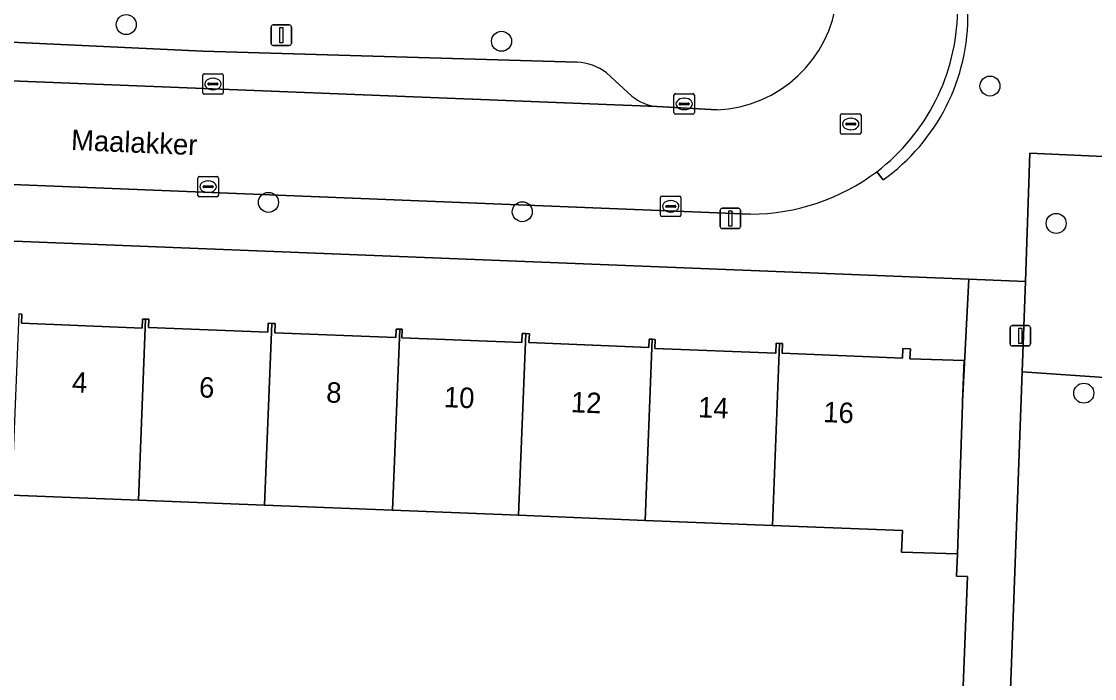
# Model space of a CAD drawing. Extents: x 161354 to 162026, y 386504 to 387460.
# Drawn here: x 161825.7 to 161878.1, y 386785.2 to 386817.3 of the extents above; entities that cross this region are included whole.
import ezdxf

# ---------------------------------------------------------------- set-up
doc = ezdxf.new("R2010")
doc.units = 0
for name, color, linetype in [('IMGEO_Boom', 7, 'Continuous'), ('IMGEO_Erf', 7, 'Continuous'), ('IMGEO_Groenvoorziening', 7, 'Continuous'), ('IMGEO_Kolk', 7, 'Continuous'), ('IMGEO_Lichtmast', 7, 'Continuous'), ('IMGEO_Openbare_ruimte_label', 7, 'Continuous'), ('IMGEO_Pand', 7, 'Continuous'), ('IMGEO_Pand_nummerreeks', 7, 'Continuous'), ('IMGEO_Parkeervlak_open', 7, 'Continuous'), ('IMGEO_Rijbaan_lokaal_open', 7, 'Continuous'), ('IMGEO_Rioolput', 7, 'Continuous'), ('IMGEO_Voetpad_open', 7, 'Continuous')]:
    doc.layers.add(name, color=color, linetype=linetype)

msp = doc.modelspace()

# ---------------------------------------------------------------- linework, layer by layer
at = {"layer": 'IMGEO_Boom'}
for centre in [(161830.824, 386817.188), (161849.159, 386816.372), (161873.02, 386814.186), (161837.772, 386808.5), (161850.172, 386808.043), (161876.252, 386807.472), (161877.602, 386799.172)]:
    msp.add_circle(centre, 0.489, dxfattribs=at)
at = {"layer": 'IMGEO_Erf'}
for points in [[(161871.979, 386804.738), (161810.187, 386807.2), (161809.981, 386807.199), (161809.775, 386807.179), (161809.572, 386807.142), (161809.373, 386807.086), (161809.18, 386807.012), (161808.994, 386806.922), (161808.817, 386806.816), (161808.651, 386806.694), (161808.496, 386806.557), (161808.353, 386806.408), (161808.225, 386806.246), (161808.111, 386806.073), (161808.014, 386805.891), (161807.933, 386805.701), (161807.869, 386805.505), (161807.824, 386805.304), (161807.799, 386805.131), (161807.308, 386800.395)], [(161825.57, 386803.047), (161825.727, 386803.04), (161825.709, 386802.588), (161831.6, 386802.353), (161831.617, 386802.797), (161831.768, 386802.791), (161831.921, 386802.785), (161831.905, 386802.381), (161837.745, 386802.148), (161837.763, 386802.591), (161837.932, 386802.584), (161838.099, 386802.578), (161838.081, 386802.127), (161843.993, 386801.891), (161844.01, 386802.309), (161844.185, 386802.302), (161844.31, 386802.297), (161844.294, 386801.881), (161850.149, 386801.647), (161850.166, 386802.089), (161850.34, 386802.082), (161850.517, 386802.075), (161850.5, 386801.644), (161856.36, 386801.41), (161856.376, 386801.816), (161856.52, 386801.81), (161856.667, 386801.804), (161856.649, 386801.362), (161862.563, 386801.126), (161862.582, 386801.609), (161862.735, 386801.603), (161862.891, 386801.597), (161862.872, 386801.123), (161868.739, 386800.889), (161868.758, 386801.352), (161869.13, 386801.337), (161869.111, 386800.856), (161871.753, 386800.766), (161871.684, 386798.765), (161871.979, 386804.738)], [(161879.556, 386799.87), (161874.587, 386800.222), (161873.877, 386780.663), (161923.762, 386778.004)], [(161871.542, 386780.734), (161871.928, 386790.211), (161871.381, 386790.22), (161871.431, 386791.311), (161868.697, 386791.399), (161868.739, 386792.453), (161862.388, 386792.707), (161856.175, 386792.955), (161849.993, 386793.202), (161843.839, 386793.448), (161837.586, 386793.698), (161831.423, 386793.945), (161825.224, 386794.192)]]:
    msp.add_lwpolyline(points, dxfattribs=at)
at = {"layer": 'IMGEO_Groenvoorziening'}
msp.add_lwpolyline([(161880.002, 386810.68), (161874.974, 386810.898), (161874.747, 386804.628), (161874.587, 386800.222), (161879.556, 386799.87), (161879.739, 386804.29)], close=True, dxfattribs=at)
at = {"layer": 'IMGEO_Kolk'}
for p, q in [((161834.559, 386813.858), (161834.559, 386814.71)), ((161834.634, 386814.784), (161835.486, 386814.784)), ((161835.047, 386814.564), (161835.072, 386814.564)), ((161835.56, 386814.71), (161835.56, 386813.858)), ((161834.818, 386814.278), (161834.818, 386814.29)), ((161835.256, 386814.241), (161834.858, 386814.241)), ((161834.861, 386814.327), (161835.259, 386814.327)), ((161835.07, 386814.004), (161835.045, 386814.004)), ((161835.302, 386814.29), (161835.302, 386814.278)), ((161835.486, 386813.784), (161834.634, 386813.784)), ((161857.581, 386812.886), (161857.581, 386813.738)), ((161857.656, 386813.812), (161858.508, 386813.812)), ((161857.883, 386813.355), (161858.281, 386813.355)), ((161858.069, 386813.592), (161858.094, 386813.592)), ((161858.582, 386813.738), (161858.582, 386812.886)), ((161858.508, 386812.812), (161857.656, 386812.812)), ((161857.84, 386813.306), (161857.84, 386813.318)), ((161858.278, 386813.269), (161857.88, 386813.269)), ((161858.092, 386813.032), (161858.067, 386813.032)), ((161858.324, 386813.318), (161858.324, 386813.306)), ((161834.324, 386808.838), (161834.324, 386809.69)), ((161834.399, 386809.764), (161835.251, 386809.764)), ((161835.325, 386809.69), (161835.325, 386808.838)), ((161834.583, 386809.258), (161834.583, 386809.27)), ((161835.021, 386809.221), (161834.623, 386809.221)), ((161834.626, 386809.307), (161835.024, 386809.307)), ((161834.812, 386809.544), (161834.837, 386809.544)), ((161835.067, 386809.27), (161835.067, 386809.258)), ((161835.251, 386808.764), (161834.399, 386808.764)), ((161834.835, 386808.984), (161834.81, 386808.984)), ((161856.923, 386807.878), (161856.923, 386808.73)), ((161856.998, 386808.804), (161857.85, 386808.804)), ((161857.924, 386808.73), (161857.924, 386807.878)), ((161857.182, 386808.298), (161857.182, 386808.31)), ((161857.62, 386808.261), (161857.222, 386808.261)), ((161857.225, 386808.347), (161857.623, 386808.347)), ((161857.411, 386808.584), (161857.436, 386808.584)), ((161857.666, 386808.31), (161857.666, 386808.298)), ((161857.85, 386807.804), (161856.998, 386807.804)), ((161857.434, 386808.024), (161857.409, 386808.024))]:
    msp.add_line(p, q, dxfattribs=at)
for points in [[(161834.559, 386813.858), (161834.559, 386814.71)], [(161834.634, 386814.784), (161835.486, 386814.784)], [(161835.56, 386814.71), (161835.56, 386813.858)], [(161835.486, 386813.784), (161834.634, 386813.784)], [(161857.581, 386812.886), (161857.581, 386813.738)], [(161857.656, 386813.812), (161858.508, 386813.812)], [(161858.582, 386813.738), (161858.582, 386812.886)], [(161858.508, 386812.812), (161857.656, 386812.812)], [(161834.324, 386808.838), (161834.324, 386809.69)], [(161834.399, 386809.764), (161835.251, 386809.764)], [(161835.325, 386809.69), (161835.325, 386808.838)], [(161835.251, 386808.764), (161834.399, 386808.764)], [(161856.923, 386807.878), (161856.923, 386808.73)], [(161856.998, 386808.804), (161857.85, 386808.804)], [(161857.924, 386808.73), (161857.924, 386807.878)], [(161857.85, 386807.804), (161856.998, 386807.804)]]:
    msp.add_lwpolyline(points, dxfattribs=at)
for centre, radius, start, end in [((161834.636, 386814.708), 0.0765, 91.552, 178.448), ((161834.636, 386814.708), 0.0765, 91.552, 178.448), ((161835.484, 386814.708), 0.0765, 1.552, 88.448), ((161835.484, 386814.708), 0.0765, 1.552, 88.448), ((161834.636, 386813.86), 0.0765, 181.552, 268.448), ((161834.636, 386813.86), 0.0765, 181.552, 268.448), ((161834.858, 386814.287), 0.0403, 85.8775, 175.7526), ((161834.855, 386814.277), 0.0366, 178.938, 274.7102), ((161835.259, 386814.284), 0.043, 264.8664, 352.4533), ((161835.263, 386814.289), 0.0386, 1.7309, 96.639), ((161835.484, 386813.86), 0.0765, 271.552, 358.448), ((161835.484, 386813.86), 0.0765, 271.552, 358.448), ((161857.658, 386813.736), 0.0765, 91.552, 178.448), ((161857.658, 386813.736), 0.0765, 91.552, 178.448), ((161857.88, 386813.315), 0.0403, 85.8775, 175.7526), ((161858.285, 386813.317), 0.0386, 1.7309, 96.639), ((161858.506, 386813.736), 0.0765, 1.552, 88.448), ((161858.506, 386813.736), 0.0765, 1.552, 88.448), ((161857.658, 386812.888), 0.0765, 181.552, 268.448), ((161857.658, 386812.888), 0.0765, 181.552, 268.448), ((161857.877, 386813.305), 0.0366, 178.938, 274.7102), ((161858.281, 386813.312), 0.043, 264.8664, 352.4533), ((161858.506, 386812.888), 0.0765, 271.552, 358.448), ((161858.506, 386812.888), 0.0765, 271.552, 358.448), ((161834.401, 386809.688), 0.0765, 91.552, 178.448), ((161834.401, 386809.688), 0.0765, 91.552, 178.448), ((161835.249, 386809.688), 0.0765, 1.552, 88.448), ((161835.249, 386809.688), 0.0765, 1.552, 88.448), ((161834.623, 386809.267), 0.0403, 85.8775, 175.7526), ((161834.62, 386809.257), 0.0366, 178.938, 274.7102), ((161835.024, 386809.264), 0.043, 264.8664, 352.4533), ((161835.028, 386809.269), 0.0386, 1.7309, 96.639), ((161834.401, 386808.84), 0.0765, 181.552, 268.448), ((161834.401, 386808.84), 0.0765, 181.552, 268.448), ((161835.249, 386808.84), 0.0765, 271.552, 358.448), ((161835.249, 386808.84), 0.0765, 271.552, 358.448), ((161857, 386808.728), 0.0765, 91.552, 178.448), ((161857, 386808.728), 0.0765, 91.552, 178.448), ((161857.848, 386808.728), 0.0765, 1.552, 88.448), ((161857.848, 386808.728), 0.0765, 1.552, 88.448), ((161857.222, 386808.307), 0.0403, 85.8775, 175.7526), ((161857.219, 386808.297), 0.0366, 178.938, 274.7102), ((161857.623, 386808.304), 0.043, 264.8664, 352.4533), ((161857.627, 386808.309), 0.0386, 1.7309, 96.639), ((161857, 386807.88), 0.0765, 181.552, 268.448), ((161857, 386807.88), 0.0765, 181.552, 268.448), ((161857.848, 386807.88), 0.0765, 271.552, 358.448), ((161857.848, 386807.88), 0.0765, 271.552, 358.448)]:
    msp.add_arc(centre, radius, start, end, dxfattribs=at)
for centre, major_axis, ratio, start_param, end_param in [((161835.046, 386814.284), (-0.387, 0.002), 0.722429, 4.712389, 7.853982), ((161835.071, 386814.284), (-0.39, 0.002), 0.717154, 1.570796, 4.712389), ((161858.068, 386813.312), (-0.387, 0.002), 0.722429, 4.712389, 7.853982), ((161858.093, 386813.312), (-0.39, 0.002), 0.717154, 1.570796, 4.712389), ((161834.811, 386809.264), (-0.387, 0.002), 0.722429, 4.712389, 7.853982), ((161834.836, 386809.264), (-0.39, 0.002), 0.717154, 1.570796, 4.712389), ((161857.41, 386808.304), (-0.387, 0.002), 0.722429, 4.712389, 7.853982), ((161857.435, 386808.304), (-0.39, 0.002), 0.717154, 1.570796, 4.712389)]:
    msp.add_ellipse(centre, major_axis=major_axis, ratio=ratio, start_param=start_param, end_param=end_param, dxfattribs=at)
at = {"layer": 'IMGEO_Lichtmast'}
for p, q in [((161837.9, 386816.271), (161837.9, 386817.071)), ((161837.9, 386817.071), (161837.9, 386816.271)), ((161838, 386817.171), (161838.79, 386817.171)), ((161838.79, 386817.171), (161838, 386817.171)), ((161838.89, 386817.071), (161838.89, 386816.271)), ((161838.89, 386816.271), (161838.89, 386817.071)), ((161838.79, 386816.171), (161838, 386816.171)), ((161838, 386816.171), (161838.79, 386816.171)), ((161859.84, 386807.314), (161859.84, 386808.114)), ((161859.84, 386808.114), (161859.84, 386807.314)), ((161859.94, 386808.214), (161860.73, 386808.214)), ((161860.73, 386808.214), (161859.94, 386808.214)), ((161860.83, 386808.114), (161860.83, 386807.314)), ((161860.83, 386807.314), (161860.83, 386808.114)), ((161860.73, 386807.214), (161859.94, 386807.214)), ((161859.94, 386807.214), (161860.73, 386807.214)), ((161874.006, 386801.579), (161874.006, 386802.379)), ((161874.006, 386802.379), (161874.006, 386801.579)), ((161874.106, 386802.479), (161874.896, 386802.479)), ((161874.896, 386802.479), (161874.106, 386802.479)), ((161874.996, 386802.379), (161874.996, 386801.579)), ((161874.996, 386801.579), (161874.996, 386802.379)), ((161874.896, 386801.479), (161874.106, 386801.479)), ((161874.106, 386801.479), (161874.896, 386801.479))]:
    msp.add_line(p, q, dxfattribs=at)
for points in [[(161838.32, 386817.046), (161838.47, 386817.046), (161838.47, 386816.296), (161838.32, 386816.296), (161838.32, 386817.046)], [(161860.26, 386808.089), (161860.41, 386808.089), (161860.41, 386807.339), (161860.26, 386807.339), (161860.26, 386808.089)], [(161874.426, 386802.354), (161874.576, 386802.354), (161874.576, 386801.604), (161874.426, 386801.604), (161874.426, 386802.354)]]:
    msp.add_lwpolyline(points, dxfattribs=at)
for centre, start, end in [((161838, 386817.071), 90, 180), ((161838, 386817.071), 90, 180), ((161838.79, 386817.071), 0, 90), ((161838.79, 386817.071), 360, 90), ((161838, 386816.271), 180, 270), ((161838, 386816.271), 180, 270), ((161838.79, 386816.271), 270, 0), ((161838.79, 386816.271), 270, 0), ((161859.94, 386808.114), 90, 180), ((161859.94, 386808.114), 90, 180), ((161860.73, 386808.114), 0, 90), ((161860.73, 386808.114), 360, 90), ((161859.94, 386807.314), 180, 270), ((161859.94, 386807.314), 180, 270), ((161860.73, 386807.314), 270, 0), ((161860.73, 386807.314), 270, 0), ((161874.106, 386802.379), 90, 180), ((161874.106, 386802.379), 90, 180), ((161874.896, 386802.379), 0, 90), ((161874.896, 386802.379), 360, 90), ((161874.106, 386801.579), 180, 270), ((161874.106, 386801.579), 180, 270), ((161874.896, 386801.579), 270, 0), ((161874.896, 386801.579), 270, 0)]:
    msp.add_arc(centre, 0.1, start, end, dxfattribs=at)
at = {"layer": 'IMGEO_Pand'}
for points in [[(161825.224, 386794.192), (161831.423, 386793.945), (161831.768, 386802.791), (161831.617, 386802.797), (161831.6, 386802.353), (161825.709, 386802.588), (161825.727, 386803.04), (161825.57, 386803.047)], [(161837.932, 386802.584), (161837.763, 386802.591), (161837.745, 386802.148), (161831.905, 386802.381), (161831.921, 386802.785), (161831.768, 386802.791), (161831.423, 386793.945), (161837.586, 386793.698)], [(161837.586, 386793.698), (161843.839, 386793.448), (161844.185, 386802.302), (161844.01, 386802.309), (161843.993, 386801.891), (161838.081, 386802.127), (161838.099, 386802.578), (161837.932, 386802.584)], [(161850.34, 386802.082), (161850.166, 386802.089), (161850.149, 386801.647), (161844.294, 386801.881), (161844.31, 386802.297), (161844.185, 386802.302), (161843.839, 386793.448), (161849.993, 386793.202)], [(161849.993, 386793.202), (161856.175, 386792.955), (161856.52, 386801.81), (161856.376, 386801.816), (161856.36, 386801.41), (161850.5, 386801.644), (161850.517, 386802.075), (161850.34, 386802.082)], [(161862.735, 386801.603), (161862.582, 386801.609), (161862.563, 386801.126), (161856.649, 386801.362), (161856.667, 386801.804), (161856.52, 386801.81), (161856.175, 386792.955), (161862.388, 386792.707)], [(161871.679, 386798.614), (161871.684, 386798.765), (161871.753, 386800.766), (161869.111, 386800.856), (161869.13, 386801.337), (161868.758, 386801.352), (161868.739, 386800.889), (161862.872, 386801.123), (161862.891, 386801.597), (161862.735, 386801.603), (161862.388, 386792.707), (161868.739, 386792.453), (161868.697, 386791.399), (161871.431, 386791.311)]]:
    msp.add_lwpolyline(points, close=True, dxfattribs=at)
at = {"layer": 'IMGEO_Parkeervlak_open'}
for points in [[(161834.57, 386815.884), (161816.522, 386816.734)], [(161852.847, 386815.353), (161834.57, 386815.884)], [(161812.486, 386814.946), (161856.748, 386813.177)], [(161855.528, 386813.688), (161854.28, 386814.826)]]:
    msp.add_lwpolyline(points, dxfattribs=at)
for centre, radius, start, end in [((161852.745, 386812.865), 2.49, 51.9554, 87.6616), ((161857.054, 386815.619), 2.461, 231.6828, 262.8642)]:
    msp.add_arc(centre, radius, start, end, dxfattribs=at)
at = {"layer": 'IMGEO_Rijbaan_lokaal_open'}
msp.add_lwpolyline([(161859.685, 386813.028), (161856.748, 386813.177), (161812.486, 386814.946), (161808.811, 386815.104), (161808.25, 386810.055), (161861.323, 386807.92)], dxfattribs=at)
for centre, radius, start, end in [((161859.433, 386819.174), 6.151, 272.3507, 353.7392), ((161861.33, 386818.018), 10.113, 307.5437, 358.9641), ((161861.26, 386818.303), 10.383, 270.3489, 306.8939)]:
    msp.add_arc(centre, radius, start, end, dxfattribs=at)
at = {"layer": 'IMGEO_Rioolput'}
for p, q in [((161865.793, 386812.828), (161866.645, 386812.828)), ((161865.718, 386811.902), (161865.718, 386812.754)), ((161865.977, 386812.322), (161865.977, 386812.334)), ((161866.415, 386812.285), (161866.017, 386812.285)), ((161866.02, 386812.371), (161866.418, 386812.371)), ((161866.206, 386812.608), (161866.231, 386812.608)), ((161866.461, 386812.334), (161866.461, 386812.322)), ((161866.719, 386812.754), (161866.719, 386811.902)), ((161866.645, 386811.828), (161865.793, 386811.828)), ((161866.229, 386812.048), (161866.204, 386812.048))]:
    msp.add_line(p, q, dxfattribs=at)
for points in [[(161865.793, 386812.828), (161866.645, 386812.828)], [(161865.718, 386811.902), (161865.718, 386812.754)], [(161866.719, 386812.754), (161866.719, 386811.902)], [(161866.645, 386811.828), (161865.793, 386811.828)]]:
    msp.add_lwpolyline(points, dxfattribs=at)
for centre, radius, start, end in [((161865.795, 386812.752), 0.0765, 91.552, 178.448), ((161865.795, 386812.752), 0.0765, 91.552, 178.448), ((161866.643, 386812.752), 0.0765, 1.552, 88.448), ((161866.643, 386812.752), 0.0765, 1.552, 88.448), ((161866.017, 386812.331), 0.0403, 85.8775, 175.7526), ((161866.014, 386812.321), 0.0366, 178.938, 274.7102), ((161866.418, 386812.328), 0.043, 264.8664, 352.4533), ((161866.422, 386812.333), 0.0386, 1.7309, 96.639), ((161865.795, 386811.904), 0.0765, 181.552, 268.448), ((161865.795, 386811.904), 0.0765, 181.552, 268.448), ((161866.643, 386811.904), 0.0765, 271.552, 358.448), ((161866.643, 386811.904), 0.0765, 271.552, 358.448)]:
    msp.add_arc(centre, radius, start, end, dxfattribs=at)
for centre, major_axis, ratio, start_param, end_param in [((161866.205, 386812.328), (-0.387, 0.002), 0.722429, 4.712389, 7.853982), ((161866.23, 386812.328), (-0.39, 0.002), 0.717154, 1.570796, 4.712389)]:
    msp.add_ellipse(centre, major_axis=major_axis, ratio=ratio, start_param=start_param, end_param=end_param, dxfattribs=at)
at = {"layer": 'IMGEO_Voetpad_open'}
for points in [[(161874.974, 386810.898), (161880.002, 386810.68), (161882.453, 386870.503), (161879.984, 386868.022), (161879.484, 386868.04), (161878.501, 386844.364), (161877.675, 386824.553)], [(161816.522, 386816.734), (161834.57, 386815.884), (161852.847, 386815.353)], [(161854.28, 386814.826), (161855.528, 386813.688)], [(161856.748, 386813.177), (161859.685, 386813.028)], [(161861.323, 386807.92), (161808.25, 386810.055), (161807.869, 386805.505), (161807.933, 386805.701), (161808.014, 386805.891), (161808.111, 386806.073), (161808.225, 386806.246), (161808.353, 386806.408), (161808.496, 386806.557), (161808.651, 386806.694), (161808.817, 386806.816), (161808.994, 386806.922), (161809.18, 386807.012), (161809.373, 386807.086), (161809.572, 386807.142), (161809.775, 386807.179), (161809.981, 386807.199), (161810.187, 386807.2), (161871.979, 386804.738), (161874.747, 386804.628), (161874.974, 386810.898)], [(161867.493, 386809.999), (161867.794, 386809.6)], [(161867.794, 386809.6), (161867.493, 386809.999)]]:
    msp.add_lwpolyline(points, dxfattribs=at)
msp.add_lwpolyline([(161874.587, 386800.222), (161874.747, 386804.628), (161871.979, 386804.738), (161871.684, 386798.765), (161871.679, 386798.614), (161871.431, 386791.311), (161871.381, 386790.22), (161871.928, 386790.211), (161871.542, 386780.734), (161871.106, 386770.041), (161870.503, 386770.041), (161870.449, 386768.915), (161870.028, 386758.279), (161869.843, 386752.696), (161872.862, 386752.607), (161872.933, 386754.57), (161873.662, 386774.698), (161873.757, 386777.335), (161873.877, 386780.663)], close=True, dxfattribs=at)
for centre, radius, start, end in [((161859.433, 386819.174), 6.151, 272.3507, 353.7392), ((161861.33, 386818.018), 10.113, 307.5437, 358.9641), ((161862.079, 386817.64), 9.865, 305.4061, 0.9846), ((161862.079, 386817.64), 9.865, 305.4061, 0.9846), ((161852.745, 386812.865), 2.49, 51.9554, 87.6616), ((161857.054, 386815.619), 2.461, 231.6828, 262.8642), ((161861.26, 386818.303), 10.383, 270.3489, 306.8939)]:
    msp.add_arc(centre, radius, start, end, dxfattribs=at)

# ---------------------------------------------------------------- texts
at = {"layer": 'IMGEO_Openbare_ruimte_label'}
msp.add_text('Maalakker', height=1, rotation=357.5926, dxfattribs=at).set_placement((161828.116, 386811.062))
at = {"layer": 'IMGEO_Pand_nummerreeks'}
for s, rotation, p in [('4', 357.7135, (161828.157, 386799.217)), ('6', 357.7135, (161834.367, 386798.969)), ('8', 357.7135, (161840.58, 386798.721)), ('10', 357.7135, (161846.329, 386798.491)), ('12', 357.7135, (161852.533, 386798.243)), ('14', 357.7135, (161858.746, 386797.995)), ('16', 357.716, (161864.862, 386797.76))]:
    msp.add_text(s, height=1, rotation=rotation, dxfattribs=at).set_placement(p)

doc.saveas('drawing.dxf')
